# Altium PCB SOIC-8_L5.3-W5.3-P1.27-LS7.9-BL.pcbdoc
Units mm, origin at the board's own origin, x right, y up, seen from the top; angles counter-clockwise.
Board outline 18.29 x 22.3 mm, 2 copper layers (Top Layer, Bottom Layer), stack 0 mm thick; 1 components, 0 nets, 8 pads, 0 vias.
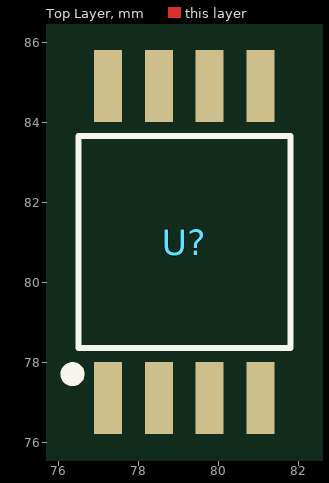
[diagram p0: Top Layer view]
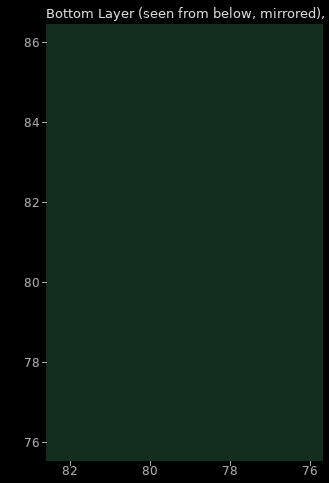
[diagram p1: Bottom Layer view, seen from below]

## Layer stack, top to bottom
Top Layer: signal copper (thickness not stored)
Bottom Layer: signal copper (thickness not stored)

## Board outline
88.144,69.85 69.85,69.85 69.85,92.15 88.144,92.15

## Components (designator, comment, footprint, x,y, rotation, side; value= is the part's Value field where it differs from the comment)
U? "" SOIC-8_L5.3-W5.3-P1.27-LS7.9-BL 79.144,81 r0 top

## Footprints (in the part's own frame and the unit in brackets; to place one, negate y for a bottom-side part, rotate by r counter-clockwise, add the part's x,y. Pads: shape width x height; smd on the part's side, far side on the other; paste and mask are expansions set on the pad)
SOIC-8_L5.3-W5.3-P1.27-LS7.9-BL [mm]
  rect 0.7x1.8 smd paste+0 mask+0.05: 1(-1.905,-3.9) 2(-0.635,-3.9) 3(0.635,-3.9) 4(1.905,-3.9) 5(1.905,3.9) 6(0.635,3.9) 7(-0.635,3.9) 8(-1.905,3.9)
  silkscreen extent -2.94,-3.45 2.65,2.65

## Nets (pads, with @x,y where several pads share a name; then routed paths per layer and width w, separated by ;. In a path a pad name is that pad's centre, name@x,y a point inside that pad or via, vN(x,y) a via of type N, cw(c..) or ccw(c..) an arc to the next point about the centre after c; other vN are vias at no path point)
pads on no net: U?.1 U?.2 U?.3 U?.4 U?.5 U?.6 U?.7 U?.8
